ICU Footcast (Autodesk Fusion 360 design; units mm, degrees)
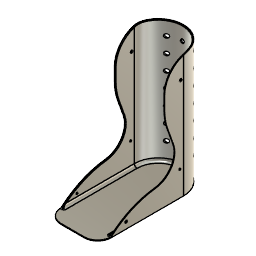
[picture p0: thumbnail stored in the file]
part number: 2025-10-02-12-56-12-317
sketch "Sketch1" plane through (0, 0, 0) normal (0, 0, 1) x axis (1, 0, 0)
  line L1 (-46.45, -158.75) -> (-46.45, 0)
  line L2 (46.45, -158.75) -> (-46.45, -158.75)
  line L3 (46.45, 0) -> (46.45, -158.75)
  line L4 (-44.45, 0) -> (-44.45, -158.75)
  line L5 (44.45, 0) -> (44.45, -158.75)
  line L6 (-44.45, 0) -> (-46.45, 0)
  line L7 (46.45, 0) -> (44.45, 0)
  line L8 (55, -133.75) -> (-58.3827, -133.75)
  circle C1 centre (0, 0) radius 46.45
  circle C2 centre (0, 0) radius 44.45
  circle C3 centre (-21.45, -133.75) radius 25
  circle C4 centre (21.45, -133.75) radius 25
  circle C5 centre (-21.45, -133.75) radius 23
  circle C6 centre (21.45, -133.75) radius 23
  point P1 (0, 0)
  point P2 (0, 0)
  point P3 (-46.45, 0)
  point P6 (46.45, 0)
  point P7 (0, 0)
  point P8 (-44.45, 0)
  point P10 (44.45, 0)
  point P11 (44.45, -158.75)
  point P9 (-44.45, -158.75)
  point P16 (-21.45, -133.75)
  coincident P1 P2
  coincident C1 P3
  tangent C1 L1
  vertical L1
  perpendicular L1 L2
  coincident C1 P6
  tangent C1 L3
  perpendicular L2 L3
  coincident P1 P7
  vertical L4
  coincident C2 P8
  vertical L5
  coincident C2 P10
  perpendicular L4 L6
  perpendicular L3 L7
  coincident L2 P11
  coincident L2 P9
  tangent L2 C4
  tangent L2 C3
  perpendicular L3 L8
  tangent L1 C3
  tangent L3 C4
  concentric C3 C5
  concentric C4 C6
  tangent L5 C6
  tangent L4 C5
  coincident L8 P16
  dimension "d2" diameter C1 = 92.9 (= "d57 + ( 2 * 2 ) * 1 mm")
  dimension "d4" distance P2 L2 = 158.75
  dimension "d57" diameter C2 = 88.9
  dimension "d73" diameter C3 = 50
  dimension "d74" diameter C4 = 50
extrude "Extrude1" new body sketch "Sketch1" profile of C1 L1 L3 L4 L5 L6 L7 L8 along normal blind 40
extrude "Extrude2" add sketch "Sketch1" profile of C1 L2 C2 L4 L5 C3 C4 L8 along normal blind 2
extrude "Extrude3" add sketch "Sketch1" profile of C1 C2 L6 L7 along normal blind 228.6
fillet "Fillet9" radius 150
work_plane "WorkPlane1" RotateAngle -90
sketch "Sketch2" plane through (46.45, 0, 0) normal (1, 0, 0) x axis (0, 1, 0)
  line L1 (0, 228.6) -> (-35, 228.6)
  line L2 (0, 40) -> (0, 228.6)
  line L3 (-35, 138.6) -> (-35, 228.6)
  line L4 (0, 40) -> (-35, 138.6)
  circle C1 centre (-5, 188.6) radius 1.75
  point P2 (0, 40)
  point P6 (0, 40)
  point P4 (0, 228.6)
  point P7 (0, 228.6)
  point P3 (-35, 228.6)
  point P5 (-35, 138.6)
  point P8 (-5, 188.6)
  horizontal L1
  perpendicular L1 L2
  perpendicular L1 L3
  coincident P2 P6
  coincident P4 P7
  dimension "d25" distance P3 P4 = 35
  dimension "d28" distance P3 P5 = 90
  dimension "d43" diameter C1 = 3.5
  dimension "d45" distance L3 P8 = 30
  dimension "d47" distance L1 P8 = 40
extrude "Extrude4" add sketch "Sketch2" against normal blind 2
mirror "Mirror1" mirrorStitchTolerance 0.1
hole "Hole1" HoleDepth 130 HoleDiameter 3.5 TipAngle 118
fillet "Fillet7" radius 0.5
work_plane "WorkPlane2" AlongDistance 46.45 (= "( 88.9 / 2 ) * 1 mm + 2 mm")
sketch "Sketch4" plane through (0, 46.45, 0) normal (0, 1, 0) x axis (1, 0, 0)
  line L1 (46.45, 0) -> (-46.45, 0)
  circle C1 centre (0, -35) radius 3.5
  circle C2 centre (0, -63) radius 3.5
  circle C3 centre (0, -91) radius 3.5
  circle C4 centre (0, -119) radius 3.5
  circle C5 centre (0, -147) radius 3.5
  circle C6 centre (0, -175) radius 3.5
  circle C7 centre (0, -203) radius 3.5
  point P2 (0, -35)
  point P3 (0, -63)
  point P4 (0, -91)
  point P5 (0, -119)
  point P6 (0, -147)
  point P7 (0, -175)
  point P8 (0, -203)
  dimension "d101" diameter C1 = 7
  dimension "d102" diameter C2 = 7 (= "d101")
  dimension "d103" diameter C3 = 7 (= "d101")
  dimension "d104" diameter C4 = 7 (= "d101")
  dimension "d105" diameter C5 = 7 (= "d101")
  dimension "d106" diameter C6 = 7 (= "d101")
  dimension "d107" diameter C7 = 7 (= "d101")
  dimension "d108" distance P2 L1 = 35
  dimension "d109" distance P2 P3 = 28
  dimension "d110" distance P3 P4 = 28 (= "d109")
  dimension "d111" distance P4 P5 = 28 (= "d109")
  dimension "d112" distance P5 P6 = 28 (= "d109")
  dimension "d113" distance P6 P7 = 28 (= "d109")
  dimension "d114" distance P7 P8 = 28 (= "d109")
extrude "Extrude13" cut sketch "Sketch4" profile of C1 C2 C3 C4 C5 C6 C7 against normal blind 130
path_pattern "PathPattern2" PathPatternDelta 131.887
fillet "Fillet14" radius 0.5
fillet "Fillet15" radius 40
fillet "Fillet16" radius 50
fillet "Fillet17" radius 100
hole "Hole2" HoleDepth 130 HoleDiameter 3.5 TipAngle 118
fillet "Fillet18" radius 5
fillet "Fillet19" radius 1
fillet "Fillet20" radius 4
